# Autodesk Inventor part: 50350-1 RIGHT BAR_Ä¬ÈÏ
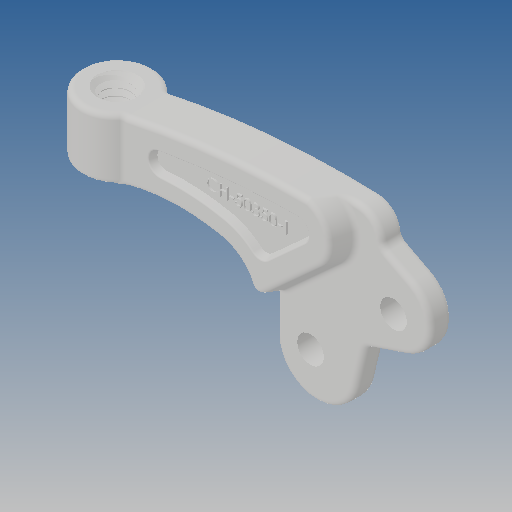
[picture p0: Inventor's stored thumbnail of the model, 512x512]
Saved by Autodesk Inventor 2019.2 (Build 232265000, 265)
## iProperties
Created: 2010-06
Part Number: 50350-1 RIGHT BAR_Ä¬ÈÏ
Material: Ogólny
Document SubType Name: Modeling
Designer: CADENGINEERING4
Density: 1 g/cm^3
Appearance: Domyślna
Author: CADENGINEERING4
Revision Number: ÈÎºÎ
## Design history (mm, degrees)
feature "NONE"
node "Bryła1"
